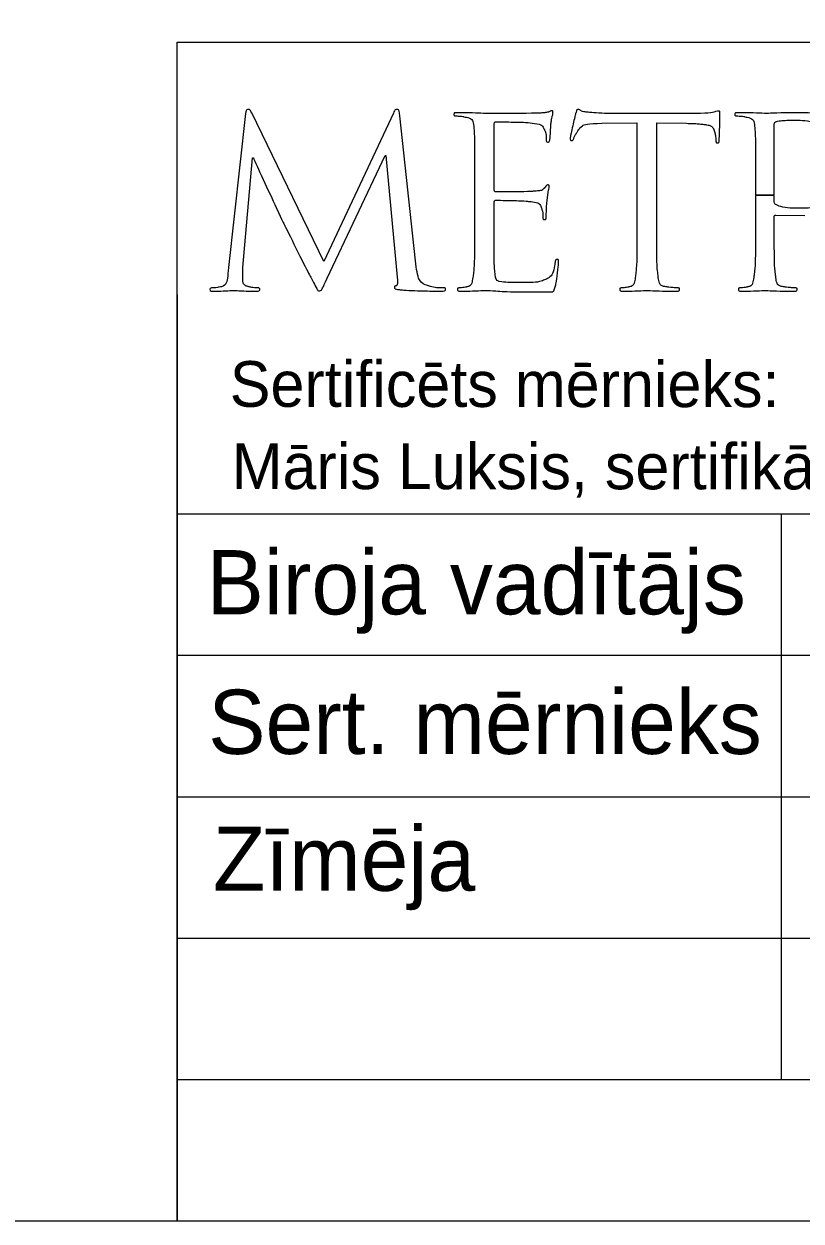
# Model space of a CAD drawing. Extents: x 321079 to 321220, y 257030 to 257220.
# Drawn here: x 321149.5 to 321163.79, y 257029.87 to 257051.88 of the extents above; entities that cross this region are included whole.
import ezdxf

# ---------------------------------------------------------------- set-up
doc = ezdxf.new("R2010")
doc.units = 0
doc.layers.add('RAMI_PLAN_####_TKST_#', color=7, linetype='Continuous')

msp = doc.modelspace()

# ---------------------------------------------------------------- linework, layer by layer
at = {"layer": 'RAMI_PLAN_####_TKST_#'}
for p, q in [((321153.575, 257050.226), (321153.263, 257047.395)), ((321156.702, 257047.521), (321156.411, 257050.187)), ((321161.851, 257050.23), (321160.222, 257050.23)), ((321158.151, 257048.832), (321158.151, 257050.031)), ((321163.301, 257048.782), (321163.301, 257050.026)), ((321162.22, 257049.809), (321162.224, 257049.761)), ((321157.786, 257048.984), (321157.786, 257048.22)), ((321162.954, 257048.731), (321163.301, 257048.731)), ((321163.301, 257048.722), (321162.954, 257048.722)), ((321162.954, 257048.722), (321162.954, 257048.22)), ((321163.301, 257048.731), (321163.301, 257048.782)), ((321158.151, 257048.22), (321158.151, 257048.602)), ((321163.301, 257048.22), (321163.301, 257048.324)), ((321163.331, 257048.359), (321163.865, 257048.351)), ((321152.317, 257046.899), (321152.318, 257029.866)), ((321218.314, 257042.859), (321152.318, 257042.859)), ((321163.426, 257042.859), (321163.426, 257032.464)), ((321191.073, 257040.261), (321152.318, 257040.261)), ((321191.073, 257037.662), (321152.318, 257037.662)), ((321210.803, 257035.063), (321152.318, 257035.063)), ((321191.073, 257032.464), (321152.318, 257032.464))]:
    msp.add_line(p, q, dxfattribs=at)
for points in [[(321079.019, 257029.866), (321079.019, 257219.866), (321218.314, 257219.866), (321218.314, 257029.866)], [(321152.318, 257051.537), (321218.314, 257051.537), (321218.314, 257029.866), (321152.318, 257029.866)]]:
    msp.add_lwpolyline(points, close=True, dxfattribs=at)
for points in [[(321156.294, 257050.235), (321155.017, 257047.508), (321153.688, 257050.239)], [(321160.131, 257050.048), (321160.774, 257050.057), (321160.774, 257048.22)], [(321161.138, 257048.22), (321161.138, 257050.057), (321161.686, 257050.048)], [(321153.527, 257047.4), (321153.701, 257049.414), (321153.719, 257049.414)], [(321155.078, 257047.2), (321156.141, 257049.457), (321156.155, 257049.457), (321156.363, 257047.218)]]:
    msp.add_lwpolyline(points, dxfattribs=at)
for points, degree in [([(321153.688, 257050.239), (321153.667, 257050.287), (321153.649, 257050.304), (321153.623, 257050.304), (321153.623, 257050.304), (321153.597, 257050.304), (321153.584, 257050.274), (321153.575, 257050.226)], 3), ([(321156.411, 257050.187), (321156.402, 257050.269), (321156.389, 257050.304), (321156.359, 257050.304), (321156.359, 257050.304), (321156.328, 257050.304), (321156.311, 257050.274), (321156.294, 257050.235)], 3), ([(321158.151, 257050.031), (321158.151, 257050.061), (321158.16, 257050.074), (321158.177, 257050.074), (321158.177, 257050.074), (321158.225, 257050.074), (321158.698, 257050.07), (321158.772, 257050.061), (321158.772, 257050.061), (321159.007, 257050.035), (321159.05, 257049.983), (321159.081, 257049.913), (321159.081, 257049.913), (321159.102, 257049.861), (321159.106, 257049.787), (321159.106, 257049.757), (321159.106, 257049.757), (321159.106, 257049.722), (321159.115, 257049.701), (321159.141, 257049.701), (321159.141, 257049.701), (321159.159, 257049.701), (321159.167, 257049.727), (321159.172, 257049.748), (321159.172, 257049.748), (321159.18, 257049.8), (321159.189, 257049.992), (321159.193, 257050.035), (321159.193, 257050.035), (321159.206, 257050.156), (321159.228, 257050.209), (321159.228, 257050.239), (321159.228, 257050.239), (321159.228, 257050.261), (321159.224, 257050.278), (321159.211, 257050.278), (321159.211, 257050.278), (321159.189, 257050.278), (321159.172, 257050.261), (321159.15, 257050.256), (321159.15, 257050.256), (321159.115, 257050.248), (321159.046, 257050.239), (321158.963, 257050.235), (321158.963, 257050.235), (321158.863, 257050.23), (321157.999, 257050.23), (321157.969, 257050.23), (321157.969, 257050.23), (321157.947, 257050.23), (321157.674, 257050.243), (321157.478, 257050.243), (321157.478, 257050.243), (321157.43, 257050.243), (321157.409, 257050.235), (321157.409, 257050.209), (321157.409, 257050.209), (321157.409, 257050.191), (321157.426, 257050.183), (321157.443, 257050.183), (321157.443, 257050.183), (321157.483, 257050.183), (321157.556, 257050.178), (321157.591, 257050.169), (321157.591, 257050.169), (321157.735, 257050.139), (321157.769, 257050.07), (321157.778, 257049.922), (321157.778, 257049.922), (321157.786, 257049.783), (321157.786, 257049.662), (321157.786, 257048.984)], 3), ([(321160.222, 257050.23), (321160.17, 257050.23), (321160.005, 257050.239), (321159.879, 257050.252), (321159.879, 257050.252), (321159.762, 257050.261), (321159.719, 257050.304), (321159.688, 257050.304), (321159.688, 257050.304), (321159.671, 257050.304), (321159.653, 257050.248), (321159.645, 257050.222), (321159.645, 257050.222), (321159.636, 257050.187), (321159.549, 257049.814), (321159.549, 257049.77), (321159.549, 257049.77), (321159.549, 257049.744), (321159.558, 257049.731), (321159.571, 257049.731), (321159.571, 257049.731), (321159.588, 257049.731), (321159.601, 257049.74), (321159.614, 257049.775), (321159.614, 257049.775), (321159.627, 257049.805), (321159.64, 257049.835), (321159.688, 257049.909), (321159.688, 257049.909), (321159.758, 257050.013), (321159.862, 257050.044), (321160.131, 257050.048)], 3), ([(321162.302, 257050.222), (321162.302, 257050.248), (321162.302, 257050.274), (321162.28, 257050.274), (321162.28, 257050.274), (321162.246, 257050.274), (321162.128, 257050.23), (321161.851, 257050.23)], 3), ([(321162.224, 257049.761), (321162.228, 257049.701), (321162.237, 257049.688), (321162.259, 257049.688), (321162.259, 257049.688), (321162.276, 257049.688), (321162.289, 257049.705), (321162.289, 257049.744), (321162.289, 257049.744), (321162.289, 257049.792), (321162.302, 257050.091), (321162.302, 257050.222)], 3), ([(321164.217, 257048.459), (321164.608, 257048.819), (321164.742, 257049.141), (321164.742, 257049.462), (321164.742, 257049.462), (321164.742, 257049.761), (321164.551, 257049.974), (321164.443, 257050.052), (321164.443, 257050.052), (321164.213, 257050.217), (321163.922, 257050.243), (321163.648, 257050.243), (321163.648, 257050.243), (321163.514, 257050.243), (321163.184, 257050.23), (321163.136, 257050.23), (321163.136, 257050.23), (321163.114, 257050.23), (321162.841, 257050.243), (321162.645, 257050.243), (321162.645, 257050.243), (321162.597, 257050.243), (321162.576, 257050.235), (321162.576, 257050.209), (321162.576, 257050.209), (321162.576, 257050.191), (321162.593, 257050.183), (321162.61, 257050.183), (321162.61, 257050.183), (321162.65, 257050.183), (321162.723, 257050.178), (321162.758, 257050.169), (321162.758, 257050.169), (321162.901, 257050.139), (321162.936, 257050.07), (321162.945, 257049.922), (321162.945, 257049.922), (321162.954, 257049.783), (321162.954, 257049.662), (321162.954, 257048.984)], 3), ([(321161.686, 257050.048), (321162.102, 257050.039), (321162.202, 257049.939), (321162.22, 257049.809)], 2), ([(321163.301, 257050.026), (321163.301, 257050.052), (321163.314, 257050.07), (321163.336, 257050.078), (321163.336, 257050.078), (321163.379, 257050.091), (321163.496, 257050.105), (321163.626, 257050.105), (321163.626, 257050.105), (321164.091, 257050.105), (321164.378, 257049.779), (321164.378, 257049.236), (321164.378, 257049.236), (321164.378, 257048.906), (321164.265, 257048.672), (321164.113, 257048.568), (321164.113, 257048.568), (321164.013, 257048.498), (321163.891, 257048.485), (321163.787, 257048.485), (321163.787, 257048.485), (321163.596, 257048.485), (321163.396, 257048.515), (321163.331, 257048.555), (321163.331, 257048.555), (321163.31, 257048.568), (321163.301, 257048.585), (321163.301, 257048.607)], 3), ([(321153.719, 257049.414), (321153.766, 257049.297), (321154.253, 257048.255), (321154.292, 257048.177), (321154.292, 257048.177), (321154.313, 257048.133), (321154.687, 257047.382), (321154.8, 257047.17), (321154.8, 257047.17), (321154.882, 257047.013), (321154.904, 257046.97), (321154.934, 257046.97), (321154.934, 257046.97), (321154.974, 257046.97), (321154.986, 257047.009), (321155.078, 257047.2)], 3), ([(321159.124, 257048.637), (321159.137, 257048.78), (321159.159, 257048.854), (321159.159, 257048.88), (321159.159, 257048.88), (321159.159, 257048.906), (321159.15, 257048.915), (321159.137, 257048.915), (321159.137, 257048.915), (321159.119, 257048.915), (321159.102, 257048.893), (321159.072, 257048.858), (321159.072, 257048.858), (321159.033, 257048.815), (321158.972, 257048.806), (321158.868, 257048.798), (321158.868, 257048.798), (321158.768, 257048.789), (321158.234, 257048.789), (321158.177, 257048.789), (321158.177, 257048.789), (321158.156, 257048.789), (321158.151, 257048.802), (321158.151, 257048.832)], 3), ([(321162.954, 257048.984), (321162.954, 257048.984), (321162.954, 257048.871), (321162.954, 257048.731)], 2), ([(321158.151, 257048.602), (321158.151, 257048.62), (321158.16, 257048.633), (321158.182, 257048.633), (321158.182, 257048.633), (321158.256, 257048.633), (321158.685, 257048.624), (321158.802, 257048.611), (321158.802, 257048.611), (321158.972, 257048.594), (321159.011, 257048.52), (321159.028, 257048.459), (321159.028, 257048.459), (321159.046, 257048.403), (321159.046, 257048.359), (321159.046, 257048.316), (321159.046, 257048.316), (321159.046, 257048.294), (321159.054, 257048.277), (321159.076, 257048.277), (321159.076, 257048.277), (321159.106, 257048.277), (321159.106, 257048.324), (321159.106, 257048.359), (321159.106, 257048.359), (321159.106, 257048.389), (321159.115, 257048.55), (321159.124, 257048.637)], 3), ([(321163.301, 257048.607), (321163.301, 257048.607), (321163.301, 257048.65), (321163.301, 257048.722)], 2), ([(321157.786, 257048.22), (321157.786, 257047.804), (321157.786, 257047.461), (321157.765, 257047.278), (321157.765, 257047.278), (321157.747, 257047.152), (321157.726, 257047.057), (321157.639, 257047.039), (321157.639, 257047.039), (321157.6, 257047.031), (321157.548, 257047.022), (321157.509, 257047.022), (321157.509, 257047.022), (321157.483, 257047.022), (321157.474, 257047.009), (321157.474, 257046.996), (321157.474, 257046.996), (321157.474, 257046.97), (321157.496, 257046.961), (321157.543, 257046.961), (321157.543, 257046.961), (321157.674, 257046.961), (321157.947, 257046.974), (321157.969, 257046.974), (321157.969, 257046.974), (321158.095, 257046.974), (321158.386, 257046.948), (321159.041, 257046.948), (321159.041, 257046.948), (321159.211, 257046.948), (321159.245, 257046.948), (321159.276, 257047.061), (321159.276, 257047.061), (321159.298, 257047.152), (321159.332, 257047.448), (321159.332, 257047.482), (321159.332, 257047.482), (321159.332, 257047.513), (321159.332, 257047.547), (321159.306, 257047.547), (321159.306, 257047.547), (321159.285, 257047.547), (321159.276, 257047.53), (321159.267, 257047.482), (321159.267, 257047.482), (321159.237, 257047.304), (321159.185, 257047.218), (321159.072, 257047.17), (321159.072, 257047.17), (321158.959, 257047.122), (321158.768, 257047.122), (321158.655, 257047.122), (321158.655, 257047.122), (321158.229, 257047.122), (321158.164, 257047.178), (321158.151, 257047.478), (321158.151, 257047.478), (321158.147, 257047.569), (321158.151, 257048.073), (321158.151, 257048.22)], 3), ([(321160.774, 257048.22), (321160.774, 257047.804), (321160.774, 257047.461), (321160.752, 257047.278), (321160.752, 257047.278), (321160.735, 257047.152), (321160.713, 257047.057), (321160.626, 257047.039), (321160.626, 257047.039), (321160.587, 257047.031), (321160.535, 257047.022), (321160.496, 257047.022), (321160.496, 257047.022), (321160.47, 257047.022), (321160.461, 257047.009), (321160.461, 257046.996), (321160.461, 257046.996), (321160.461, 257046.97), (321160.483, 257046.961), (321160.531, 257046.961), (321160.531, 257046.961), (321160.661, 257046.961), (321160.934, 257046.974), (321160.956, 257046.974), (321160.956, 257046.974), (321160.978, 257046.974), (321161.251, 257046.961), (321161.49, 257046.961), (321161.49, 257046.961), (321161.538, 257046.961), (321161.56, 257046.974), (321161.56, 257046.996), (321161.56, 257046.996), (321161.56, 257047.009), (321161.551, 257047.022), (321161.525, 257047.022), (321161.525, 257047.022), (321161.486, 257047.022), (321161.39, 257047.031), (321161.33, 257047.039), (321161.33, 257047.039), (321161.199, 257047.057), (321161.173, 257047.152), (321161.16, 257047.278), (321161.16, 257047.278), (321161.138, 257047.461), (321161.138, 257047.804), (321161.138, 257048.22)], 3), ([(321162.954, 257048.22), (321162.954, 257047.804), (321162.954, 257047.461), (321162.932, 257047.278), (321162.932, 257047.278), (321162.914, 257047.152), (321162.893, 257047.057), (321162.806, 257047.039), (321162.806, 257047.039), (321162.767, 257047.031), (321162.715, 257047.022), (321162.676, 257047.022), (321162.676, 257047.022), (321162.65, 257047.022), (321162.641, 257047.009), (321162.641, 257046.996), (321162.641, 257046.996), (321162.641, 257046.97), (321162.663, 257046.961), (321162.71, 257046.961), (321162.71, 257046.961), (321162.841, 257046.961), (321163.114, 257046.974), (321163.119, 257046.974), (321163.119, 257046.974), (321163.14, 257046.974), (321163.414, 257046.961), (321163.653, 257046.961), (321163.653, 257046.961), (321163.7, 257046.961), (321163.722, 257046.974), (321163.722, 257046.996), (321163.722, 257046.996), (321163.722, 257047.009), (321163.713, 257047.022), (321163.687, 257047.022), (321163.687, 257047.022), (321163.648, 257047.022), (321163.553, 257047.031), (321163.492, 257047.039), (321163.492, 257047.039), (321163.362, 257047.057), (321163.336, 257047.152), (321163.323, 257047.278), (321163.323, 257047.278), (321163.301, 257047.461), (321163.301, 257047.804), (321163.301, 257048.22)], 3), ([(321163.301, 257048.324), (321163.301, 257048.346), (321163.31, 257048.359), (321163.331, 257048.359)], 2), ([(321156.363, 257047.218), (321156.372, 257047.139), (321156.367, 257047.065), (321156.346, 257047.061), (321156.346, 257047.061), (321156.324, 257047.057), (321156.315, 257047.048), (321156.315, 257047.031), (321156.315, 257047.031), (321156.315, 257047.009), (321156.337, 257046.996), (321156.437, 257046.987), (321156.437, 257046.987), (321156.598, 257046.974), (321157.067, 257046.961), (321157.162, 257046.961), (321157.162, 257046.961), (321157.214, 257046.961), (321157.253, 257046.974), (321157.253, 257047), (321157.253, 257047), (321157.253, 257047.018), (321157.24, 257047.022), (321157.218, 257047.022), (321157.218, 257047.022), (321157.175, 257047.022), (321157.062, 257047.022), (321156.936, 257047.061), (321156.936, 257047.061), (321156.749, 257047.122), (321156.719, 257047.365), (321156.702, 257047.521)], 3), ([(321152.915, 257047), (321152.915, 257046.97), (321152.946, 257046.961), (321152.989, 257046.961), (321152.989, 257046.961), (321153.106, 257046.961), (321153.315, 257046.974), (321153.354, 257046.974), (321153.354, 257046.974), (321153.389, 257046.974), (321153.597, 257046.961), (321153.758, 257046.961), (321153.758, 257046.961), (321153.81, 257046.961), (321153.836, 257046.97), (321153.836, 257047), (321153.836, 257047), (321153.836, 257047.013), (321153.818, 257047.022), (321153.801, 257047.022), (321153.801, 257047.022), (321153.775, 257047.022), (321153.71, 257047.026), (321153.636, 257047.044), (321153.636, 257047.044), (321153.571, 257047.057), (321153.523, 257047.113), (321153.523, 257047.178), (321153.523, 257047.178), (321153.523, 257047.252), (321153.523, 257047.33), (321153.527, 257047.4)], 3), ([(321153.263, 257047.395), (321153.245, 257047.23), (321153.232, 257047.061), (321153.089, 257047.035), (321153.089, 257047.035), (321153.024, 257047.022), (321152.993, 257047.022), (321152.959, 257047.022), (321152.959, 257047.022), (321152.937, 257047.022), (321152.915, 257047.013), (321152.915, 257047)], 3)]:
    msp.add_open_spline(points, degree=degree, dxfattribs=at)

# ---------------------------------------------------------------- texts
for s, p in [('Sertificēts mērnieks:', (321153.284, 257044.836)), ('Māris Luksis, sertifikāts Nr. BC-203', (321153.319, 257043.324))]:
    msp.add_text(s, height=0.84, rotation=359.9635, dxfattribs=at).set_placement(p)
for s, height, p in [('Biroja vadītājs', 1.18124, (321152.857, 257041.02)), ('Sert. mērnieks', 1.18125, (321152.888, 257038.453)), ('Zīmēja', 1.1812, (321152.972, 257035.937))]:
    msp.add_text(s, height=height, dxfattribs=at).set_placement(p)

doc.saveas('drawing.dxf')
